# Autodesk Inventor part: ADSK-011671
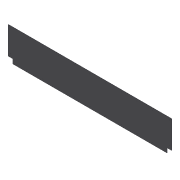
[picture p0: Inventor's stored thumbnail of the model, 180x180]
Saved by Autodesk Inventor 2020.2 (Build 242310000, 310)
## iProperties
Created: 2000-02
Part Number: ADSK-011671
Document SubType Name: Blech
Description: PLT-XX,FA,XX,O1,820,160, NON-SKID STEP FOR HOPPER
Designer: sspink
Material: 1.0312 DC05
Density: 1 g/cm^3
Sheet Metal Rule: Stahlblech 1.0312 - DC05 -   3.0 mm
Appearance: Metal-Steel(Polish)
Mass: 2510.9 g
Surface Area: 16906 cm^2
Volume: 2510.9 cm^3
Flat Pattern Width: 40.6 cm
Flat Pattern Length: 208 cm
Flat Pattern Area: 8444.8 cm^2
Sheet Metal Width: 406,000 mm
Sheet Metal Length: 2080,000 mm
Sheet Metal Area: 844480,000 mm^2
Control State: 0
Checked Out: False
Master: False
Shininess: 35.0
Length Units: 11269
Angle Units: 11279
Time Units: 11290
Mass Units: 11283
Length Display Precision: 3
Angle Display Precision: 2
Compacted: True
Cutlength: 82.00 x 16.00 (1312 SI)
Material Desc: SHEET,ALUM,.125 DIAMOND TREAD
Material_Number: A098413
Dimensions: 406x3x2080 mm
Mass: 2,511 kg
Semi finished: Stahlblech 1.0312 - DC05 -   3.0 mm
VLT_Material: 1.0312 DC05
DocNumber: ADSK-011671.ipt
Folder: .
VDS_Category: 3D Komponenten
G_L: 406x2080 mm
Thickness: 3,000 mm
Density: 2.71
Volumn: 1950.060616000001
Area: 12416.104200000005
PropertySet Name: Model Information
Author: sspink
Revision Number: -
Title: cover
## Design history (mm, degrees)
node "Face1"
  sketch "Sketch1"
    geometry: L1 (-1040, -203)-(1040, -203); L2 (1040, -203)-(1040, 203); L3 (1040, 203)-(-1040, 203); L4 (-1040, 203)-(-1040, -203); 3 further points
    constraints: 8 end point, 2 midpoint, 2 parallel, 1 horizontal, 1 horizontal alignment, 1 perpendicular, 1 vertical alignment
    dimensions: "d0" = 406 distance of L3.end L1.start; "d1" = 2080 distance between parallel lines of L2 L4
node "Cut1" dims "d14" = 3 (= Thickness), "d15" = 0
  sketch "Sketch3"
    geometry: L1 (2080, 0)-(0, 0) reference; L2 (2080, 406)-(2080, 0) reference; L3 (0, 0)-(0, 406) reference; L4 (0, 57)-(57, 57); L5 (57, 57)-(57, 0); L6 (2023, 0)-(2023, 57); L7 (2023, 57)-(2080, 57)
    constraints: 8 end point, 4 point on line, 3 perpendicular, 1 parallel
    dimensions: "d10" = 57 distance between parallel lines of L5 L3 (= d12); "d11" = 57 distance between parallel lines of L4 L1 (= d12); "d12" = 57 distance between parallel lines of L7 L1; "d13" = 57 distance between parallel lines of L6 L2 (= d12)
node "Hole1" dims "d22" = 5.5, "d23" = 10.4, "d24" = 6.35, "d25" = 90 deg, "d26" = 19.05, "d27" = 118 deg, "d43" = 6
  sketch "Sketch4"
    geometry: L1 (2023, -406)-(57, -406) reference; L2 (2080, 0)-(2080, -349) reference; L3 (0, 0)-(2080, 0) reference; L4 (0, -349)-(0, 0) reference; 4 further points
    constraints: 2 vertical alignment
    dimensions: "d16" = 25 distance from line of point (25, -25) L4 (= d19); "d17" = 25 distance from line of point (25, -25) L3 (= d20); "d18" = 100 distance from line of point (25, -306) L1 (= d21); "d19" = 25 distance from line of point (2055, -25) L2; "d20" = 25 distance from line of point (2055, -25) L3; "d21" = 100 distance from line of point (2055, -306) L1; "d46" = 281 distance of point (25, -306) point (25, -25) (derived)
node "Hole2" dims "d30" = 5.5, "d31" = 10.4, "d32" = 6.35, "d33" = 90 deg, "d34" = 19.05, "d35" = 118 deg, "d44" = 6
  sketch "Sketch5"
    geometry: L1 (0, 0)-(2080, 0) reference; L2 (1040, 0)-(1040, -406); L3 (2023, -406)-(57, -406) reference; 2 further points
    constraints: 2 end point, 2 midpoint, 2 point on line, 1 vertical
    dimensions: "d28" = 25 distance from line of point (1040, -25) L1; "d45" = 25 distance from line of L3 point (1040, -381) (= d28)
node "Rectangular Pattern1" dims "d36" = 90, "d38" = 200, "d41" = 0
node "Solide1"
node "Corps solides"
node "Corps surfaciques"
node "Plate1" dims "d42" = 3 (= Thickness)
feature "Definition1"
other parameters: "Thickness" = 3 (derived), "BendRadius" = 3 (= Thickness), "BendReliefWidth" = 3 (= Thickness), "BendReliefDepth" = 1.5 (= 0.5 x Thickness), "CornerReliefSize" = 12 (= 4 x Thickness), "SeamGap" = 0.00508, "MinimumRemnant" = 6 (= 2 x Thickness), "d2" = 3 (= BendRadius), "TransitionRadius" = 3 (= BendRadius), "TailleRayonJacobi" = 3 (= BendRadius), "TailleJeu" = 3 (= Thickness), "KFaktor" = 4.4, "BendRadius" = 3, "BendReliefDepth" = 1.5, "BendReliefWidth" = 3, "CornerReliefSize" = 12, "MinimumRemnant" = 6, "TailleJeu" = 3, "TailleRayonJacobi" = 3, "Thickness" = 3, "TransitionRadius" = 3
